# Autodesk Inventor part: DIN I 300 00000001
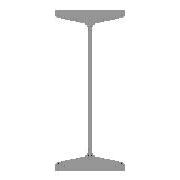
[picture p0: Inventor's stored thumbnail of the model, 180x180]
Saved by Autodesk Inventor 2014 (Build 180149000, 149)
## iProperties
IsCustomPart: 1
Created: 2009-11
Part Number: DIN I 300 00000001
Material: Steel, Mild
Description: Hot rolled I-beam
Document SubType Name: Modeling
Standard: DIN
Designer: pokornp
Standard Revision: 1995
Standards Organization: DIN
Language: en-US
Size Designation: I 300
Categories: <MemberInstance><Categories><Category DisplayName="Structural Shapes" InternalName="089c4875-fa83-4c05-b084-43b9cc11f5ed" Mnemonic="GRDR"><CategoryParameter Dis
Stock Number: I 300
Density: 7.86 g/cm^3
Sheet Metal Rule: Default
Appearance: Steel
_CCFamilyMember: 120
_CCFamilyDisplayName: DIN 1025-1 - Hot rolled I-beam
_FrameMemberDoc: Frame Member File
_Version: 15.0.0
G_L: 10000.000 mm
G_W: 125.000 mm
G_H: 300.000 mm
Author: pokornp
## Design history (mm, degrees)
node "Start plane"
node "End plane"
sketch "Sketch"
  geometry: L1 (5.4, -120.788)-(5.4, 120.788); L2 (-62.5, -150)-(62.5, -150); L3 (-5.4, 120.788)-(-5.4, -120.788); L4 (62.5, 150)-(-62.5, 150); L5 (0, -210)-(0, 210) reference; L6 (-89.185, 0)-(89.185, 0) reference; L7 (-62.5, 150)-(-62.5, 143.828); L8 (-56.901, 137.391)-(-14.703, 131.483); L9 (62.5, 150)-(62.5, 143.828); L10 (56.901, 137.391)-(14.703, 131.483); L11 (-56.901, -137.391)-(-14.703, -131.483); L12 (14.703, -131.483)-(56.901, -137.391); L13 (62.5, -143.828)-(62.5, -150); L14 (-62.5, -150)-(-62.5, -143.828); A1 r 6.5 centre (-56, 143.828) between (-62.5, 143.828) and (-56.901, 137.391); A2 r 6.5 centre (56, 143.828) between (56.901, 137.391) and (62.5, 143.828); A3 r 6.5 centre (56, -143.828) between (62.5, -143.828) and (56.901, -137.391); A4 r 6.5 centre (-56, -143.828) between (-56.901, -137.391) and (-62.5, -143.828); A5 r 10.8 centre (-16.2, 120.788) between (-5.4, 120.788) and (-14.703, 131.483); A6 r 10.8 centre (16.2, 120.788) between (14.703, 131.483) and (5.4, 120.788); A7 r 10.8 centre (16.2, -120.788) between (5.4, -120.788) and (14.703, -131.483); A8 r 10.8 centre (-16.2, -120.788) between (-14.703, -131.483) and (-5.4, -120.788); 6 further points
  constraints: 24 end point, 16 point on circle, 16 tangent, 9 point on line, 8 centre point, 6 equal radius, 4 equal length, 3 parallel, 2 horizontal, 2 vertical, 1 perpendicular, 1 symmetric about line, 3 other
  dimensions: "d3" = 300 vertical distance of L2.end L4.end (= ParH); "d17" = 125 distance of L4.start L4.end (= b); "d22" = 10.8 distance between parallel lines of L3 L1 (= t1); "d28" = 150 distance between parallel lines of L2 L6 (= 0.5 x d3); "d31" = 7.96961 deg angle of L4 L8; "d32" = 31.25 distance from line of point (31.25, -133.8) L13 (= 0.25 x b); "d33" = 16.2 distance from line of L2 point (31.25, -133.8) (= t2); "d34" = 6.5 radius of A1 (= R1); "d35" = 10.8 radius of A5 (= R)
extrude "Body" new body sketch "Sketch" stored distance "d18" = 10000 (= G_L); taper "d19" = 0 deg
node "Driven Length"
  sketch "Sketch3"
    geometry: L1 (0, 0)-(10, 0) reference
    constraints: 2 end point, 1 horizontal
  workplane "Work Plane7"
  sketch "Sketch4"
    geometry: L1 (-2, 0)-(12, 0) reference; L2 (-2, 10000)-(12, 10000) reference
    dimensions: "d37" = 10000 distance between parallel lines of L1 L2 (derived)
body "Solid1"
other parameters: "b" = 125 [user parameter; used in 4 equation terms], "ParH" = 300 [user parameter; used in 1 equation term], "R1" = 6.5 [user parameter; used in 1 equation term], "t1" = 10.8 [user parameter; used in 2 equation terms], "t2" = 16.2 [user parameter; used in 1 equation term], "msp_pom" = 51.7 (= 0.5 x b - t1) [user parameter; used in 1 equation term], "msp_x1" = 3.619 (= 0.07 x msp_pom) [user parameter], "msp_x2" = 4.375 (= 0.035 x b) [user parameter], "G_L" = 10000 (= d37) [user parameter; used in 1 equation term], "R" = 10.8 [user parameter; used in 1 equation term], "d4" = 4.25 (derived), "d6" = 7.47 (derived), "d8" = 0 (derived), "d10" = 0 (derived), "d12" = 4.25 (derived), "d14" = 4.25 (derived), "G_OFFSET_START" = 0 [user parameter; used in 1 equation term], "G_OFFSET_END" = 0 [user parameter; used in 1 equation term], "d29" = 0 (computed from G_OFFSET_START), "Thickness" = 0.5, "BendRadius" = 0.5 (= Thickness), "BendReliefWidth" = 0.5 (= Thickness), "BendReliefDepth" = 0.25 (= 0.5 x Thickness), "CornerReliefSize" = 2 (= 4 x Thickness), "SeamGap" = 0.01, "MinimumRemnant" = 1 (= 2 x Thickness), "TransitionRadius" = 0.5 (= BendRadius), "JacobiRadiusSize" = 0.5 (= Thickness), "d36" = 90 deg, "GapSize" = 0.5 (= Thickness)
